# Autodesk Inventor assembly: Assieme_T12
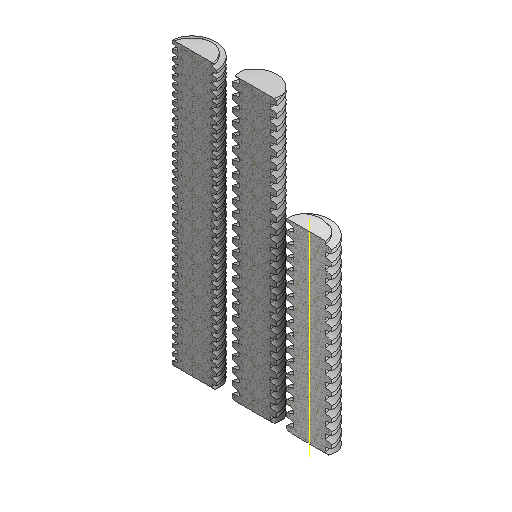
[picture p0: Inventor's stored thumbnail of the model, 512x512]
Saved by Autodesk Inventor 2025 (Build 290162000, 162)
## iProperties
Created: 2024-10
Part Number: Assieme_T12
Document SubType Name: Assembly
Designer: R5800u
Author: R5800u
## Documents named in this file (3)
- C:\Users\R5800u\Desktop\Assieme_T12.iam
- C:\Users\R5800u\Desktop\BARRA FILETTATA T12 615mm p2mm 2P.ipt
- C:\Users\R5800u\Desktop\t12v2.ipt
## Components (2 placed, 2 different names)
1. BARRA FILETTATA T12 615mm p2mm 2P:1 — Coincidente:4
2. t12v2:1
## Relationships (1: Mate 1)
- Coincidente:4 [Mate]: BARRA FILETTATA T12 615mm p2mm 2P:1
